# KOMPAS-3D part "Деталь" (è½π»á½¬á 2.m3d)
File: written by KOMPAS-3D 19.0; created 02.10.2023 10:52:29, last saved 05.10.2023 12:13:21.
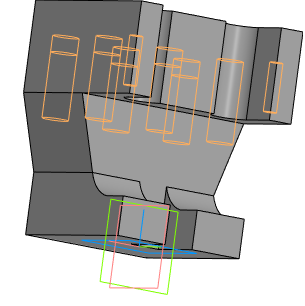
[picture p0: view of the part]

Document properties: Автор: admin; Организация: Hewlett-Packard Company; Полное имя файла: C:\Users\Petrenko-VE\Documents\Клупалка_2.m3d

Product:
- Part/product: Деталь
    Масса: 8.68496

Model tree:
1. Эскиз:1
2. Элемент выдавливания:1
     Расстояние 1 = 24
3. Эскиз:2  (with: Элемент выдавливания:1)
4. Элемент выдавливания:2
     Расстояние 2 = 35
5. Эскиз:3  (with: Элемент выдавливания:1)
6. Элемент выдавливания:3
     Расстояние 1 = 60
7. Эскиз:4  (with: Элемент выдавливания:3, Элемент выдавливания:1)
8. Элемент выдавливания:4
     Расстояние 1 = 30
9. Эскиз:5  (with: Элемент выдавливания:4)
10. Элемент выдавливания:5
     Расстояние 2 = 40
11. Эскиз:6  (with: Элемент выдавливания:4)
12. Эскиз:7  (with: Элемент выдавливания:1)
13. Элемент выдавливания:6
     Расстояние 2 = 30
14. Эскиз:8  (with: Элемент выдавливания:4, Элемент выдавливания:6)
15. Элемент выдавливания:7
     Расстояние 1 = 60
16. Эскиз:9  (with: Элемент выдавливания:2, Элемент выдавливания:7)
17. Элемент выдавливания:8
     Расстояние 2 = 75
18. Эскиз:10  (with: Элемент выдавливания:4)
19. Элемент выдавливания:9
     Расстояние 2 = 30
20. Эскиз:11  (with: Элемент выдавливания:4, Элемент выдавливания:9)
21. Элемент выдавливания:10
     Расстояние 1 = 60
22. Эскиз:12  (with: Элемент выдавливания:2, Элемент выдавливания:10)
23. Элемент выдавливания:11
     Расстояние 2 = 75
24. Эскиз:13  (with: Элемент выдавливания:4, Элемент выдавливания:5)
25. Элемент выдавливания:12
     Расстояние 2 = 40
26. Фаска:1  (with: Элемент выдавливания:3)
     Угол = 48.8141; Длина 1 = 14; Длина 2 = 16
27. Фаска:2  (with: Элемент выдавливания:3)
     Угол = 48.8141; Длина 1 = 14; Длина 2 = 16
28. Эскиз:14  (with: Элемент выдавливания:2, Фаска:1)
29. Элемент выдавливания:13
     Расстояние 1 = 150
30. Эскиз:15  (with: Элемент выдавливания:1, Элемент выдавливания:8)
31. Элемент выдавливания:14
     Расстояние 1 = 10
32. Эскиз:16  (with: Элемент выдавливания:1, Элемент выдавливания:11)
33. Элемент выдавливания:16
     Расстояние 1 = 10
34. Эскиз:17  (with: Элемент выдавливания:2, Элемент выдавливания:11, Элемент выдавливания:16)
35. Элемент выдавливания:17
     Расстояние 2 = 75
36. Эскиз:18  (with: Элемент выдавливания:2, Элемент выдавливания:8, Элемент выдавливания:14)
37. Элемент выдавливания:18
     Расстояние 2 = 75
38. Эскиз:19  (with: Элемент выдавливания:4)
39. Элемент выдавливания:19  (with: Элемент выдавливания:4)
     Расстояние 1 = 6
40. Эскиз:20  (with: Элемент выдавливания:19)
41. Элемент выдавливания:20
     Расстояние 2 = 50
42. Эскиз:21  (with: Элемент выдавливания:19)
43. Элемент выдавливания:21
     Расстояние 2 = 30
44. Условное изображение резьбы:1  (with: Элемент выдавливания:20)  (labels: M16; cil0_24705-2004 coarse)
     Длина резьбы = 10; Шаг резьбы = 2; Номинальный диаметр резьбы = 16
45. Подгонка:1  (with: Элемент выдавливания:20)
46. Условное изображение резьбы:2  (with: Элемент выдавливания:20)  (labels: M16; cil0_24705-2004 coarse)
     Длина резьбы = 10; Шаг резьбы = 2; Номинальный диаметр резьбы = 16
47. Подгонка:2  (with: Элемент выдавливания:20)
48. Условное изображение резьбы:3  (with: Элемент выдавливания:20)  (labels: M16; cil0_24705-2004 coarse)
     Длина резьбы = 10; Шаг резьбы = 2; Номинальный диаметр резьбы = 16
49. Подгонка:3  (with: Элемент выдавливания:20)
50. Условное изображение резьбы:4  (with: Элемент выдавливания:20)  (labels: M16; cil0_24705-2004 coarse)
     Длина резьбы = 10; Шаг резьбы = 2; Номинальный диаметр резьбы = 16
51. Подгонка:4  (with: Элемент выдавливания:20)
52. Условное изображение резьбы:5  (with: Элемент выдавливания:20)  (labels: M16; cil0_24705-2004 coarse)
     Длина резьбы = 10; Шаг резьбы = 2; Номинальный диаметр резьбы = 16
53. Подгонка:5  (with: Элемент выдавливания:20)
54. Условное изображение резьбы:6  (with: Элемент выдавливания:20)  (labels: M16; cil0_24705-2004 coarse)
     Длина резьбы = 50; Шаг резьбы = 2; Номинальный диаметр резьбы = 16
55. Подгонка:6  (with: Элемент выдавливания:20)
56. Условное изображение резьбы:7  (with: Элемент выдавливания:20)  (labels: M16; cil0_24705-2004 coarse)
     Длина резьбы = 50; Шаг резьбы = 2; Номинальный диаметр резьбы = 16
57. Подгонка:7  (with: Элемент выдавливания:20)
58. Условное изображение резьбы:8  (with: Элемент выдавливания:20)  (labels: M16; cil0_24705-2004 coarse)
     Длина резьбы = 50; Шаг резьбы = 2; Номинальный диаметр резьбы = 16
59. Подгонка:8  (with: Элемент выдавливания:20)
60. Условное изображение резьбы:9  (with: Элемент выдавливания:20)  (labels: M16; cil0_24705-2004 coarse)
     Длина резьбы = 50; Шаг резьбы = 2; Номинальный диаметр резьбы = 16
61. Подгонка:9  (with: Элемент выдавливания:20)
62. Условное изображение резьбы:10  (with: Элемент выдавливания:20)  (labels: M16; cil0_24705-2004 coarse)
     Длина резьбы = 50; Шаг резьбы = 2; Номинальный диаметр резьбы = 16
63. Подгонка:10  (with: Элемент выдавливания:20)
64. Условное изображение резьбы:11  (with: Элемент выдавливания:20)  (labels: M16; cil0_24705-2004 coarse)
     Длина резьбы = 50; Шаг резьбы = 2; Номинальный диаметр резьбы = 16
65. Подгонка:11  (with: Элемент выдавливания:20)
66. Условное изображение резьбы:12  (with: Элемент выдавливания:21)  (labels: M8; cil0_24705-2004 coarse)
     Длина резьбы = 30; Шаг резьбы = 1.25; Номинальный диаметр резьбы = 8
67. Подгонка:12  (with: Элемент выдавливания:21)
68. Условное изображение резьбы:13  (with: Элемент выдавливания:21)  (labels: M8; cil0_24705-2004 coarse)
     Длина резьбы = 30; Шаг резьбы = 1.25; Номинальный диаметр резьбы = 8
69. Подгонка:13  (with: Элемент выдавливания:21)
70. Эскиз:22  (with: Элемент выдавливания:19)
71. Элемент выдавливания:22  (with: Элемент выдавливания:19)
     Расстояние 1 = 20
72. Эскиз:23  (with: Элемент выдавливания:22)
73. Элемент выдавливания:25  (with: Элемент выдавливания:2)
     Расстояние 2 = 14
74. Эскиз:24  (with: Элемент выдавливания:2, Элемент выдавливания:13, Элемент выдавливания:17, Элемент выдавливания:18)
75. Элемент выдавливания:26
     Расстояние 2 = 14
76. Эскиз:25  (with: Элемент выдавливания:1, Элемент выдавливания:26)
77. Элемент выдавливания:27
     Расстояние 2 = 105
78. Эскиз:26  (with: Элемент выдавливания:1, Элемент выдавливания:2)
79. Элемент выдавливания:28
     Расстояние 2 = 14
80. Эскиз:27  (with: Элемент выдавливания:1, Элемент выдавливания:27)
81. Элемент выдавливания:29
     Расстояние 2 = 35
82. Эскиз:28  (with: Элемент выдавливания:1, Элемент выдавливания:27)
83. Элемент выдавливания:30
     Расстояние 2 = 35
84. Эскиз:29  (with: Элемент выдавливания:20)
85. Элемент выдавливания:31
     Расстояние 1 = 20
86. Эскиз:30  (with: Элемент выдавливания:20)
87. Элемент выдавливания:32
     Расстояние 1 = 20
88. Эскиз:31  (with: Элемент выдавливания:20)
89. Элемент выдавливания:33
     Расстояние 1 = 20
90. Эскиз:32  (with: Элемент выдавливания:9, Элемент выдавливания:17)
91. Элемент выдавливания:34
     Расстояние 2 = 120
